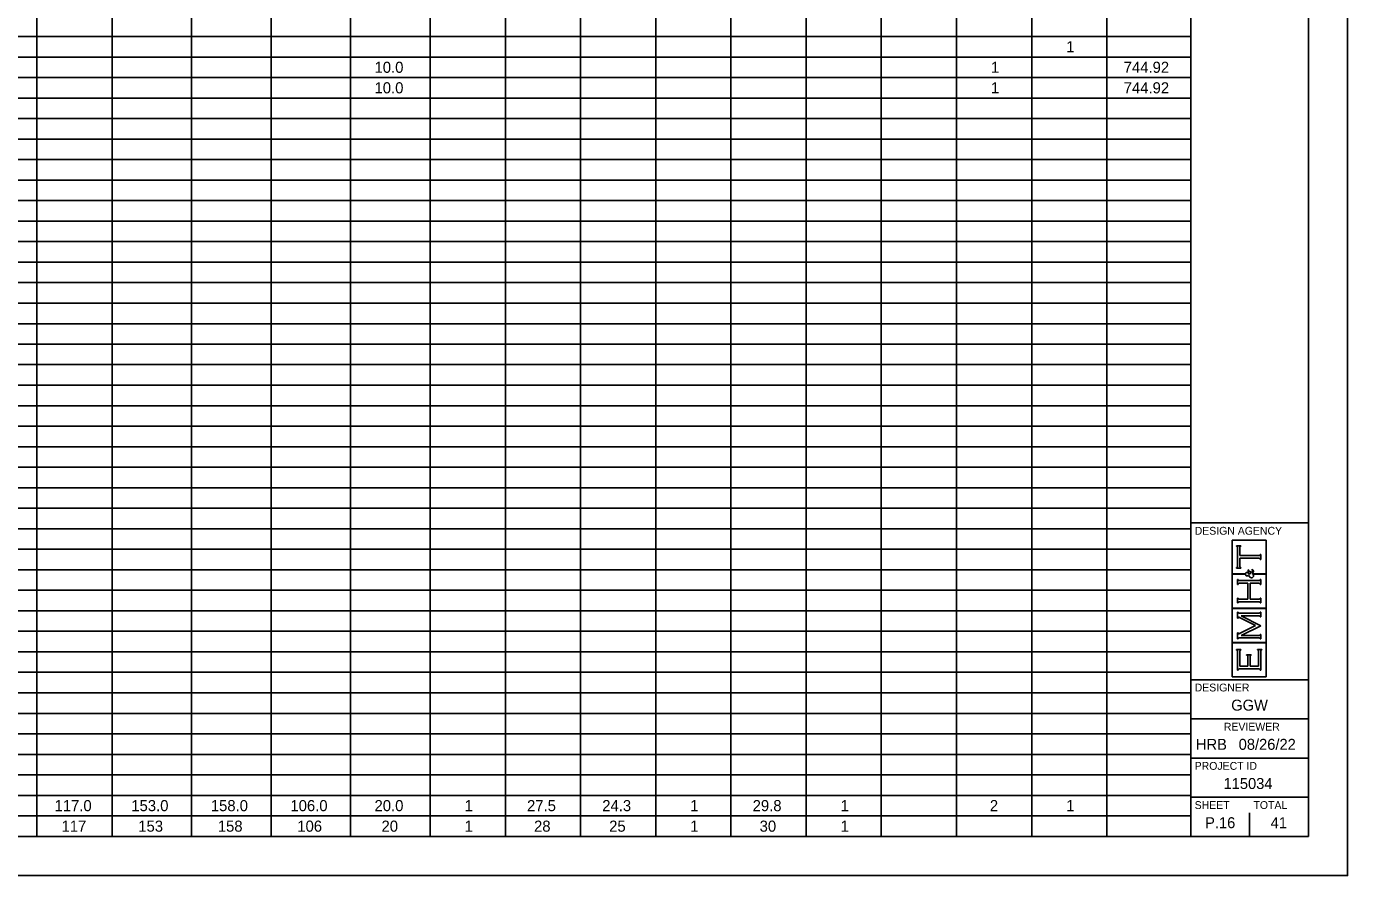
# Model space of a CAD drawing. Extents: x 0 to 34, y 0 to 22.
# Drawn here: x 17.15 to 34, y 0 to 10.84 of the extents above; entities that cross this region are included whole.
import ezdxf

# ---------------------------------------------------------------- set-up
doc = ezdxf.new("R2010")
doc.units = 0
for name, color, linetype in [('SH_Border', 7, 'Continuous'), ('SH_Cut_Line', 7, 'Continuous'), ('SH_Data', 7, 'Continuous'), ('SH_Text', 7, 'Continuous')]:
    doc.layers.add(name, color=color, linetype=linetype)

msp = doc.modelspace()

# ---------------------------------------------------------------- linework, layer by layer
at = {"layer": 'SH_Border'}
for p, q in [((32, 0.5), (32, 21.5)), ((32, 4.5), (33.5, 4.5)), ((32, 2.5), (33.5, 2.5)), ((32, 2), (33.5, 2)), ((32, 1.5), (33.5, 1.5)), ((32, 1), (33.5, 1))]:
    msp.add_line(p, q, dxfattribs=at)
msp.add_lwpolyline([(1.5, 21.5), (33.5, 21.5), (33.5, 0.5), (1.5, 0.5)], close=True, dxfattribs=at)
at = {"layer": 'SH_Cut_Line'}
msp.add_lwpolyline([(0, 0), (34, 0), (34, 22), (0, 22)], close=True, dxfattribs=at)
at = {"layer": 'SH_Data'}
for p, q in [((32.962, 4.282), (32.53, 4.282)), ((32.53, 4.282), (32.53, 3.85)), ((32.962, 3.85), (32.962, 4.282)), ((32.584, 4.202), (32.584, 4.209)), ((32.584, 4.209), (32.64, 4.209)), ((32.589, 4.201), (32.584, 4.202)), ((32.593, 4.199), (32.589, 4.201)), ((32.595, 4.196), (32.593, 4.199)), ((32.597, 4.194), (32.595, 4.196)), ((32.598, 4.189), (32.597, 4.194)), ((32.598, 4.183), (32.598, 4.189)), ((32.598, 3.949), (32.598, 4.183)), ((32.627, 4.194), (32.626, 4.189)), ((32.626, 4.189), (32.626, 4.183)), ((32.626, 4.183), (32.626, 4.083)), ((32.626, 4.083), (32.868, 4.083)), ((32.868, 4.049), (32.626, 4.049)), ((32.626, 4.049), (32.626, 3.949)), ((32.629, 4.196), (32.627, 4.194)), ((32.631, 4.199), (32.629, 4.196)), ((32.634, 4.201), (32.631, 4.199)), ((32.64, 4.202), (32.634, 4.201)), ((32.64, 4.209), (32.64, 4.202)), ((32.868, 4.083), (32.874, 4.083)), ((32.874, 4.049), (32.868, 4.049)), ((32.874, 4.083), (32.878, 4.084)), ((32.878, 4.048), (32.874, 4.049)), ((32.878, 4.084), (32.881, 4.086)), ((32.881, 4.047), (32.878, 4.048)), ((32.881, 4.086), (32.883, 4.088)), ((32.883, 4.045), (32.881, 4.047)), ((32.883, 4.088), (32.885, 4.092)), ((32.885, 4.041), (32.883, 4.045)), ((32.885, 4.092), (32.886, 4.097)), ((32.886, 4.097), (32.893, 4.097)), ((32.893, 4.097), (32.893, 4.035)), ((32.584, 3.931), (32.589, 3.932)), ((32.584, 3.924), (32.584, 3.931)), ((32.64, 3.924), (32.584, 3.924)), ((32.589, 3.932), (32.593, 3.934)), ((32.593, 3.934), (32.595, 3.936)), ((32.595, 3.936), (32.597, 3.939)), ((32.597, 3.939), (32.598, 3.943)), ((32.598, 3.943), (32.598, 3.949)), ((32.626, 3.949), (32.626, 3.943)), ((32.626, 3.943), (32.627, 3.939)), ((32.627, 3.939), (32.629, 3.936)), ((32.629, 3.936), (32.631, 3.934)), ((32.631, 3.934), (32.634, 3.932)), ((32.634, 3.932), (32.64, 3.931)), ((32.64, 3.931), (32.64, 3.924)), ((32.734, 3.87), (32.734, 3.9)), ((32.734, 3.9), (32.736, 3.9)), ((32.736, 3.9), (32.737, 3.896)), ((32.737, 3.896), (32.738, 3.893)), ((32.738, 3.893), (32.739, 3.891)), ((32.739, 3.891), (32.741, 3.889)), ((32.74, 3.876), (32.739, 3.874)), ((32.742, 3.877), (32.74, 3.876)), ((32.741, 3.889), (32.745, 3.886)), ((32.745, 3.877), (32.742, 3.877)), ((32.745, 3.886), (32.753, 3.882)), ((32.752, 3.877), (32.745, 3.877)), ((32.76, 3.872), (32.752, 3.877)), ((32.753, 3.882), (32.761, 3.877)), ((32.761, 3.877), (32.768, 3.873)), ((32.777, 3.902), (32.779, 3.905)), ((32.781, 3.901), (32.777, 3.902)), ((32.779, 3.905), (32.786, 3.903)), ((32.779, 3.871), (32.783, 3.875)), ((32.783, 3.899), (32.781, 3.901)), ((32.785, 3.897), (32.783, 3.899)), ((32.783, 3.875), (32.785, 3.879)), ((32.787, 3.895), (32.785, 3.897)), ((32.785, 3.879), (32.787, 3.882)), ((32.786, 3.903), (32.791, 3.9)), ((32.788, 3.892), (32.787, 3.895)), ((32.787, 3.882), (32.788, 3.885)), ((32.788, 3.889), (32.788, 3.892)), ((32.788, 3.885), (32.788, 3.889)), ((32.791, 3.9), (32.794, 3.896)), ((32.794, 3.896), (32.797, 3.892)), ((32.797, 3.892), (32.799, 3.888)), ((32.799, 3.878), (32.798, 3.874)), ((32.799, 3.888), (32.799, 3.882)), ((32.799, 3.882), (32.799, 3.878)), ((32.886, 4.035), (32.885, 4.041)), ((32.893, 4.035), (32.886, 4.035)), ((32.53, 3.85), (32.689, 3.85)), ((32.688, 3.845), (32.53, 3.845)), ((32.53, 3.845), (32.53, 3.413)), ((32.598, 3.716), (32.598, 3.778)), ((32.598, 3.778), (32.605, 3.778)), ((32.605, 3.716), (32.598, 3.716)), ((32.605, 3.778), (32.606, 3.773)), ((32.606, 3.722), (32.605, 3.716)), ((32.606, 3.773), (32.608, 3.769)), ((32.608, 3.726), (32.606, 3.722)), ((32.608, 3.769), (32.61, 3.767)), ((32.61, 3.728), (32.608, 3.726)), ((32.61, 3.767), (32.613, 3.765)), ((32.613, 3.729), (32.61, 3.728)), ((32.613, 3.765), (32.617, 3.764)), ((32.617, 3.73), (32.613, 3.729)), ((32.617, 3.764), (32.623, 3.764)), ((32.623, 3.73), (32.617, 3.73)), ((32.623, 3.764), (32.868, 3.764)), ((32.727, 3.73), (32.623, 3.73)), ((32.689, 3.85), (32.688, 3.845)), ((32.697, 3.855), (32.698, 3.859)), ((32.697, 3.849), (32.697, 3.855)), ((32.697, 3.843), (32.697, 3.849)), ((32.698, 3.838), (32.697, 3.843)), ((32.698, 3.859), (32.702, 3.863)), ((32.702, 3.833), (32.698, 3.838)), ((32.702, 3.863), (32.705, 3.867)), ((32.706, 3.827), (32.702, 3.833)), ((32.705, 3.867), (32.709, 3.868)), ((32.712, 3.824), (32.706, 3.827)), ((32.709, 3.868), (32.714, 3.868)), ((32.721, 3.824), (32.712, 3.824)), ((32.714, 3.868), (32.719, 3.868)), ((32.719, 3.868), (32.724, 3.867)), ((32.723, 3.824), (32.721, 3.824)), ((32.727, 3.824), (32.723, 3.824)), ((32.724, 3.867), (32.728, 3.863)), ((32.73, 3.825), (32.727, 3.824)), ((32.727, 3.527), (32.727, 3.73)), ((32.728, 3.863), (32.731, 3.86)), ((32.733, 3.826), (32.73, 3.825)), ((32.731, 3.86), (32.736, 3.853)), ((32.737, 3.827), (32.733, 3.826)), ((32.736, 3.87), (32.734, 3.87)), ((32.737, 3.872), (32.736, 3.87)), ((32.736, 3.853), (32.74, 3.844)), ((32.739, 3.874), (32.737, 3.873)), ((32.737, 3.873), (32.737, 3.872)), ((32.742, 3.829), (32.737, 3.827)), ((32.74, 3.844), (32.751, 3.851)), ((32.748, 3.818), (32.742, 3.829)), ((32.754, 3.81), (32.748, 3.818)), ((32.751, 3.851), (32.761, 3.857)), ((32.76, 3.806), (32.754, 3.81)), ((32.868, 3.73), (32.756, 3.73)), ((32.756, 3.73), (32.756, 3.527)), ((32.77, 3.864), (32.76, 3.872)), ((32.766, 3.802), (32.76, 3.806)), ((32.761, 3.857), (32.77, 3.864)), ((32.772, 3.8), (32.766, 3.802)), ((32.768, 3.873), (32.774, 3.867)), ((32.778, 3.8), (32.772, 3.8)), ((32.774, 3.867), (32.779, 3.871)), ((32.783, 3.8), (32.778, 3.8)), ((32.788, 3.802), (32.783, 3.8)), ((32.79, 3.862), (32.785, 3.857)), ((32.785, 3.857), (32.79, 3.851)), ((32.793, 3.807), (32.788, 3.802)), ((32.794, 3.866), (32.79, 3.862)), ((32.79, 3.851), (32.794, 3.846)), ((32.797, 3.811), (32.793, 3.807)), ((32.796, 3.87), (32.794, 3.866)), ((32.794, 3.846), (32.796, 3.841)), ((32.798, 3.874), (32.796, 3.87)), ((32.796, 3.841), (32.798, 3.836)), ((32.799, 3.818), (32.797, 3.811)), ((32.798, 3.836), (32.799, 3.831)), ((32.803, 3.845), (32.799, 3.85)), ((32.799, 3.85), (32.962, 3.85)), ((32.799, 3.831), (32.799, 3.826)), ((32.799, 3.826), (32.799, 3.818)), ((32.962, 3.845), (32.803, 3.845)), ((32.868, 3.764), (32.874, 3.764)), ((32.874, 3.73), (32.868, 3.73)), ((32.874, 3.764), (32.878, 3.765)), ((32.878, 3.729), (32.874, 3.73)), ((32.878, 3.765), (32.881, 3.767)), ((32.881, 3.728), (32.878, 3.729)), ((32.881, 3.767), (32.883, 3.769)), ((32.883, 3.726), (32.881, 3.728)), ((32.883, 3.769), (32.885, 3.773)), ((32.885, 3.722), (32.883, 3.726)), ((32.885, 3.773), (32.886, 3.778)), ((32.886, 3.716), (32.885, 3.722)), ((32.886, 3.778), (32.893, 3.778)), ((32.893, 3.716), (32.886, 3.716)), ((32.893, 3.778), (32.893, 3.716)), ((32.962, 3.413), (32.962, 3.845)), ((32.598, 3.479), (32.598, 3.541)), ((32.598, 3.541), (32.605, 3.541)), ((32.605, 3.541), (32.606, 3.535)), ((32.885, 3.535), (32.886, 3.541)), ((32.886, 3.541), (32.893, 3.541)), ((32.893, 3.541), (32.893, 3.479)), ((32.53, 3.413), (32.962, 3.413)), ((32.961, 3.407), (32.53, 3.407)), ((32.53, 3.407), (32.53, 2.975)), ((32.605, 3.479), (32.598, 3.479)), ((32.606, 3.485), (32.605, 3.479)), ((32.606, 3.535), (32.608, 3.532)), ((32.608, 3.488), (32.606, 3.485)), ((32.608, 3.532), (32.61, 3.53)), ((32.61, 3.49), (32.608, 3.488)), ((32.61, 3.53), (32.613, 3.528)), ((32.613, 3.492), (32.61, 3.49)), ((32.613, 3.528), (32.617, 3.527)), ((32.617, 3.493), (32.613, 3.492)), ((32.617, 3.527), (32.623, 3.527)), ((32.623, 3.493), (32.617, 3.493)), ((32.623, 3.527), (32.727, 3.527)), ((32.868, 3.493), (32.623, 3.493)), ((32.75, 3.5), (32.75, 3.5)), ((32.756, 3.527), (32.868, 3.527)), ((32.868, 3.527), (32.874, 3.527)), ((32.874, 3.493), (32.868, 3.493)), ((32.874, 3.527), (32.878, 3.528)), ((32.878, 3.492), (32.874, 3.493)), ((32.878, 3.528), (32.881, 3.53)), ((32.881, 3.49), (32.878, 3.492)), ((32.881, 3.53), (32.883, 3.532)), ((32.883, 3.489), (32.881, 3.49)), ((32.883, 3.532), (32.885, 3.535)), ((32.885, 3.485), (32.883, 3.489)), ((32.886, 3.479), (32.885, 3.485)), ((32.893, 3.479), (32.886, 3.479)), ((32.961, 2.975), (32.961, 3.407)), ((32.598, 3.285), (32.598, 3.362)), ((32.598, 3.362), (32.605, 3.362)), ((32.605, 3.285), (32.598, 3.285)), ((32.605, 3.362), (32.606, 3.357)), ((32.607, 3.292), (32.605, 3.285)), ((32.606, 3.357), (32.608, 3.353)), ((32.61, 3.296), (32.607, 3.292)), ((32.608, 3.353), (32.61, 3.351)), ((32.61, 3.351), (32.613, 3.349)), ((32.614, 3.296), (32.61, 3.296)), ((32.613, 3.349), (32.617, 3.349)), ((32.617, 3.296), (32.614, 3.296)), ((32.617, 3.349), (32.623, 3.349)), ((32.622, 3.294), (32.617, 3.296)), ((32.629, 3.291), (32.622, 3.294)), ((32.623, 3.349), (32.868, 3.349)), ((32.827, 3.191), (32.629, 3.291)), ((32.868, 3.315), (32.644, 3.315)), ((32.644, 3.315), (32.893, 3.189)), ((32.868, 3.349), (32.874, 3.349)), ((32.874, 3.315), (32.868, 3.315)), ((32.874, 3.349), (32.878, 3.349)), ((32.878, 3.314), (32.874, 3.315)), ((32.878, 3.349), (32.881, 3.351)), ((32.881, 3.312), (32.878, 3.314)), ((32.881, 3.351), (32.883, 3.353)), ((32.883, 3.31), (32.881, 3.312)), ((32.883, 3.353), (32.885, 3.357)), ((32.885, 3.306), (32.883, 3.31)), ((32.885, 3.357), (32.886, 3.362)), ((32.886, 3.301), (32.885, 3.306)), ((32.886, 3.362), (32.893, 3.362)), ((32.893, 3.301), (32.886, 3.301)), ((32.893, 3.362), (32.893, 3.301)), ((32.598, 3.02), (32.598, 3.096)), ((32.598, 3.096), (32.605, 3.096)), ((32.605, 3.096), (32.607, 3.089)), ((32.607, 3.089), (32.61, 3.086)), ((32.61, 3.086), (32.614, 3.086)), ((32.617, 3.034), (32.613, 3.033)), ((32.614, 3.086), (32.615, 3.086)), ((32.615, 3.086), (32.621, 3.088)), ((32.623, 3.034), (32.617, 3.034)), ((32.621, 3.088), (32.63, 3.093)), ((32.868, 3.034), (32.623, 3.034)), ((32.63, 3.093), (32.827, 3.191)), ((32.893, 3.189), (32.644, 3.064)), ((32.644, 3.064), (32.868, 3.064)), ((32.868, 3.064), (32.874, 3.064)), ((32.874, 3.034), (32.868, 3.034)), ((32.874, 3.064), (32.878, 3.065)), ((32.878, 3.033), (32.874, 3.034)), ((32.878, 3.065), (32.88, 3.067)), ((32.88, 3.067), (32.883, 3.069)), ((32.883, 3.069), (32.885, 3.073)), ((32.885, 3.073), (32.886, 3.078)), ((32.886, 3.078), (32.893, 3.078)), ((32.893, 3.078), (32.893, 3.02)), ((32.53, 2.975), (32.961, 2.975)), ((32.961, 2.969), (32.53, 2.969)), ((32.53, 2.969), (32.53, 2.538)), ((32.584, 2.877), (32.584, 2.884)), ((32.584, 2.884), (32.64, 2.884)), ((32.589, 2.875), (32.584, 2.877)), ((32.593, 2.873), (32.589, 2.875)), ((32.595, 2.871), (32.593, 2.873)), ((32.597, 2.868), (32.595, 2.871)), ((32.598, 2.864), (32.597, 2.868)), ((32.605, 3.02), (32.598, 3.02)), ((32.606, 3.025), (32.605, 3.02)), ((32.608, 3.029), (32.606, 3.025)), ((32.61, 3.031), (32.608, 3.029)), ((32.613, 3.033), (32.61, 3.031)), ((32.627, 2.868), (32.626, 2.864)), ((32.629, 2.871), (32.627, 2.868)), ((32.631, 2.873), (32.629, 2.871)), ((32.635, 2.875), (32.631, 2.873)), ((32.64, 2.877), (32.635, 2.875)), ((32.64, 2.884), (32.64, 2.877)), ((32.851, 2.88), (32.851, 2.887)), ((32.851, 2.887), (32.907, 2.887)), ((32.857, 2.878), (32.851, 2.88)), ((32.86, 2.877), (32.857, 2.878)), ((32.862, 2.874), (32.86, 2.877)), ((32.864, 2.871), (32.862, 2.874)), ((32.865, 2.867), (32.864, 2.871)), ((32.865, 2.861), (32.865, 2.867)), ((32.881, 3.031), (32.878, 3.033)), ((32.883, 3.029), (32.881, 3.031)), ((32.885, 3.025), (32.883, 3.029)), ((32.886, 3.02), (32.885, 3.025)), ((32.893, 3.02), (32.886, 3.02)), ((32.894, 2.871), (32.893, 2.867)), ((32.893, 2.867), (32.893, 2.861)), ((32.896, 2.874), (32.894, 2.871)), ((32.898, 2.876), (32.896, 2.874)), ((32.902, 2.878), (32.898, 2.876)), ((32.907, 2.88), (32.902, 2.878)), ((32.907, 2.887), (32.907, 2.88)), ((32.961, 2.538), (32.961, 2.969)), ((32.598, 2.858), (32.598, 2.864)), ((32.598, 2.623), (32.598, 2.858)), ((32.626, 2.864), (32.626, 2.858)), ((32.626, 2.858), (32.626, 2.671)), ((32.713, 2.812), (32.713, 2.819)), ((32.713, 2.819), (32.769, 2.819)), ((32.719, 2.811), (32.713, 2.812)), ((32.722, 2.809), (32.719, 2.811)), ((32.724, 2.806), (32.722, 2.809)), ((32.726, 2.804), (32.724, 2.806)), ((32.727, 2.799), (32.726, 2.804)), ((32.727, 2.793), (32.727, 2.799)), ((32.727, 2.671), (32.727, 2.793)), ((32.758, 2.806), (32.756, 2.804)), ((32.756, 2.804), (32.756, 2.799)), ((32.756, 2.799), (32.756, 2.793)), ((32.756, 2.793), (32.756, 2.671)), ((32.76, 2.809), (32.758, 2.806)), ((32.764, 2.811), (32.76, 2.809)), ((32.769, 2.812), (32.764, 2.811)), ((32.769, 2.819), (32.769, 2.812)), ((32.865, 2.671), (32.865, 2.861)), ((32.893, 2.861), (32.893, 2.623)), ((32.53, 2.538), (32.961, 2.538)), ((32.605, 2.623), (32.598, 2.623)), ((32.606, 2.629), (32.605, 2.623)), ((32.608, 2.632), (32.606, 2.629)), ((32.61, 2.634), (32.608, 2.632)), ((32.613, 2.636), (32.61, 2.634)), ((32.617, 2.637), (32.613, 2.636)), ((32.623, 2.637), (32.617, 2.637)), ((32.868, 2.637), (32.623, 2.637)), ((32.626, 2.671), (32.727, 2.671)), ((32.756, 2.671), (32.865, 2.671)), ((32.874, 2.637), (32.868, 2.637)), ((32.878, 2.636), (32.874, 2.637)), ((32.881, 2.634), (32.878, 2.636)), ((32.883, 2.633), (32.881, 2.634)), ((32.885, 2.629), (32.883, 2.633)), ((32.886, 2.623), (32.885, 2.629)), ((32.893, 2.623), (32.886, 2.623)), ((32.375, 0.675), (32.375, 0.675)), ((32.75, 0.5), (32.75, 0.8))]:
    msp.add_line(p, q, dxfattribs=at)
at = {"layer": 'SH_Text'}
for p, q in [((17.285, 21.5), (17.285, 0.5)), ((18.244, 21.5), (18.244, 0.5)), ((19.258, 21.5), (19.258, 0.5)), ((20.272, 21.5), (20.272, 0.5)), ((21.286, 21.5), (21.286, 0.5)), ((22.3, 21.5), (22.3, 0.5)), ((23.259, 21.5), (23.259, 0.5)), ((24.218, 21.5), (24.218, 0.5)), ((25.177, 21.5), (25.177, 0.5)), ((26.136, 21.5), (26.136, 0.5)), ((27.095, 21.5), (27.095, 0.5)), ((28.054, 21.5), (28.054, 0.5)), ((29.013, 21.5), (29.013, 0.5)), ((32, 21.5), (32, 0.5)), ((29.972, 21.007), (29.972, 0.5)), ((30.93, 21.007), (30.93, 0.5)), ((1.5, 10.707), (32, 10.707)), ((1.5, 10.446), (32, 10.446)), ((1.5, 10.184), (32, 10.184)), ((1.5, 9.922), (32, 9.922)), ((1.5, 9.661), (32, 9.661)), ((1.5, 9.399), (32, 9.399)), ((1.5, 9.137), (32, 9.137)), ((1.5, 8.875), (32, 8.875)), ((1.5, 8.614), (32, 8.614)), ((1.5, 8.352), (32, 8.352)), ((1.5, 8.09), (32, 8.09)), ((1.5, 7.828), (32, 7.828)), ((1.5, 7.567), (32, 7.567)), ((1.5, 7.305), (32, 7.305)), ((1.5, 7.043), (32, 7.043)), ((1.5, 6.782), (32, 6.782)), ((1.5, 6.52), (32, 6.52)), ((1.5, 6.258), (32, 6.258)), ((1.5, 5.996), (32, 5.996)), ((1.5, 5.735), (32, 5.735)), ((1.5, 5.473), (32, 5.473)), ((1.5, 5.211), (32, 5.211)), ((1.5, 4.949), (32, 4.949)), ((1.5, 4.688), (32, 4.688)), ((1.5, 4.426), (32, 4.426)), ((1.5, 4.164), (32, 4.164)), ((1.5, 3.902), (32, 3.902)), ((1.5, 3.641), (32, 3.641)), ((1.5, 3.379), (32, 3.379)), ((1.5, 3.117), (32, 3.117)), ((1.5, 2.856), (32, 2.856)), ((1.5, 2.594), (32, 2.594)), ((1.5, 2.332), (32, 2.332)), ((1.5, 2.07), (32, 2.07)), ((1.5, 1.809), (32, 1.809)), ((1.5, 1.547), (32, 1.547)), ((1.5, 1.285), (32, 1.285)), ((1.5, 1.023), (32, 1.023)), ((1.5, 0.762), (32, 0.762)), ((1.5, 0.5), (32, 0.5))]:
    msp.add_line(p, q, dxfattribs=at)

# ---------------------------------------------------------------- texts
at = {"layer": 'SH_Data'}
for s, height, p in [('DESIGN AGENCY', 0.1, (32.05, 4.35)), ('DESIGNER', 0.1, (32.05, 2.35)), ('GGW', 0.14, (32.516, 2.105)), ('REVIEWER', 0.1, (32.422, 1.85)), ('HRB', 0.14, (32.066, 1.605)), ('08/26/22', 0.14, (32.611, 1.605)), ('PROJECT ID', 0.1, (32.05, 1.35)), ('115034', 0.14, (32.418, 1.105)), ('SHEET', 0.1, (32.05, 0.85)), ('TOTAL', 0.1, (32.8, 0.85)), ('P.16', 0.14, (32.183, 0.605)), ('41', 0.14, (33.019, 0.605))]:
    msp.add_text(s, height=height, dxfattribs=at).set_placement(p)
at = {"layer": 'SH_Text'}
for s, height, p in [('1', 0.142, (30.411, 10.506)), ('10.0', 0.1416, (21.591, 10.244)), ('1', 0.142, (29.452, 10.244)), ('744.92', 0.1416, (31.145, 10.244)), ('10.0', 0.1416, (21.591, 9.982)), ('1', 0.142, (29.452, 9.982)), ('744.92', 0.1416, (31.145, 9.982)), ('117.0', 0.1416, (17.51, 0.822)), ('153.0', 0.1416, (18.489, 0.822)), ('158.0', 0.1416, (19.503, 0.822)), ('106.0', 0.1416, (20.518, 0.822)), ('20.0', 0.1416, (21.591, 0.822)), ('1', 0.142, (22.74, 0.822)), ('27.5', 0.1416, (23.536, 0.822)), ('24.3', 0.1416, (24.495, 0.822)), ('1', 0.142, (25.617, 0.822)), ('29.8', 0.1416, (26.413, 0.822)), ('1', 0.142, (27.535, 0.822)), ('2', 0.142, (29.438, 0.822)), ('1', 0.142, (30.411, 0.822)), ('117', 0.1416, (17.599, 0.56)), ('153', 0.1416, (18.578, 0.56)), ('158', 0.1416, (19.592, 0.56)), ('106', 0.1416, (20.606, 0.56)), ('20', 0.1416, (21.68, 0.56)), ('1', 0.142, (22.74, 0.56)), ('28', 0.1416, (23.625, 0.56)), ('25', 0.1416, (24.583, 0.56)), ('1', 0.142, (25.617, 0.56)), ('30', 0.1416, (26.502, 0.56)), ('1', 0.142, (27.535, 0.56))]:
    msp.add_text(s, height=height, dxfattribs=at).set_placement(p)

doc.saveas('drawing.dxf')
